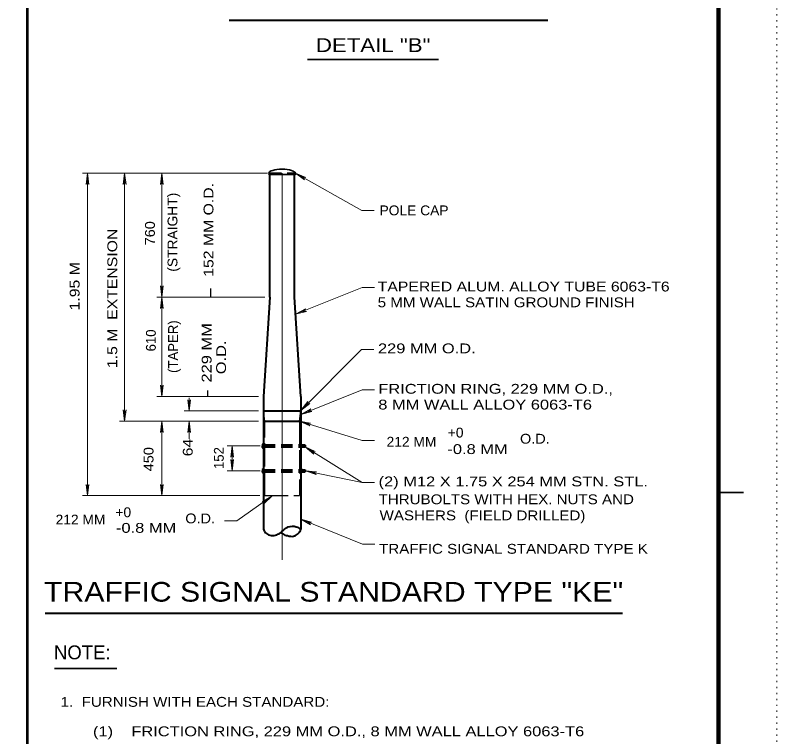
# Model space of a CAD drawing. Extents: x 312583 to 312854, y 144419 to 144597.
# Drawn here: x 312794.6 to 312853.5, y 144484.7 to 144540.5 of the extents above; entities that cross this region are included whole.
import ezdxf

# ---------------------------------------------------------------- set-up
doc = ezdxf.new("R2010")
doc.units = 0
doc.header["$LTSCALE"] = 0.3
for name, pattern in [('DOTTED', [1.5, 0.3, -1.2]), ('LONG_DASHED', [7.5, 6, -1.5]), ('MEDIUM_DASHED', [4.5, 3, -1.5])]:
    doc.linetypes.add(name, pattern=pattern)
for name, color, linetype, lineweight in [('1', 7, 'Continuous', 40), ('2', 7, 'Continuous', 13), ('62', 7, 'DOTTED', 13)]:
    doc.layers.add(name, color=color, linetype=linetype, lineweight=lineweight)

msp = doc.modelspace()

# ---------------------------------------------------------------- linework, layer by layer
at = {"layer": '1', "lineweight": 158}
msp.add_line((312849, 144423.1446), (312849, 144585.0846), dxfattribs=at)
at = {"layer": '1', "lineweight": 35}
for p, q in [((312814.2381, 144528.2019), (312814.2381, 144528.2709)), ((312813.7934, 144507.0803), (312813.8011, 144507.0803)), ((312813.7934, 144505.1636), (312813.8011, 144505.1636)), ((312849, 144503.6216), (312850.932, 144503.6216))]:
    msp.add_line(p, q, dxfattribs=at)
at = {"layer": '1', "linetype": 'MEDIUM_DASHED', "lineweight": 35}
for p, q in [((312814.2994, 144528.3016), (312816.2161, 144528.3016)), ((312814.2994, 144528.2019), (312814.2994, 144528.3016)), ((312816.2161, 144528.3016), (312816.2161, 144528.2019))]:
    msp.add_line(p, q, dxfattribs=at)
at = {"layer": '1', "lineweight": 25}
for p, q in [((312809.7454, 144518.7183), (312809.7454, 144519.4006)), ((312809.5077, 144511.0516), (312809.5077, 144511.5039))]:
    msp.add_line(p, q, dxfattribs=at)
at = {"layer": '1'}
for p, q in [((312813.7321, 144507.3256), (312813.7321, 144507.2183)), ((312813.7321, 144507.1109), (312813.7321, 144507.2259)), ((312813.7397, 144507.3563), (312813.8241, 144507.3563)), ((312813.7397, 144507.2873), (312813.8241, 144507.2873)), ((312813.7397, 144507.1493), (312813.8241, 144507.1493)), ((312813.7397, 144507.0803), (312813.8241, 144507.0803)), ((312816.7834, 144507.3563), (312816.6991, 144507.3563)), ((312816.7834, 144507.2873), (312816.6991, 144507.2873)), ((312816.7834, 144507.1569), (312816.6991, 144507.1569)), ((312816.7834, 144507.0879), (312816.6991, 144507.0879)), ((312816.7911, 144507.3256), (312816.7911, 144507.2183)), ((312816.7911, 144507.1109), (312816.7911, 144507.2183)), ((312813.7321, 144505.4089), (312813.7321, 144505.3016)), ((312813.7321, 144505.1943), (312813.7321, 144505.3093)), ((312813.7397, 144505.4396), (312813.8241, 144505.4396)), ((312813.7397, 144505.3706), (312813.8241, 144505.3706)), ((312813.7397, 144505.2326), (312813.8241, 144505.2326)), ((312813.7397, 144505.1636), (312813.8241, 144505.1636)), ((312816.7834, 144505.4396), (312816.6991, 144505.4396)), ((312816.7834, 144505.3706), (312816.6991, 144505.3706)), ((312816.7834, 144505.2403), (312816.6991, 144505.2403)), ((312816.7834, 144505.1713), (312816.6991, 144505.1713)), ((312816.7911, 144505.4089), (312816.7911, 144505.3016)), ((312816.7911, 144505.1943), (312816.7911, 144505.3016))]:
    msp.add_line(p, q, dxfattribs=at)
at = {"layer": '1', "lineweight": 53}
msp.add_lwpolyline([(312849, 144468.4167), (312795.5728, 144468.4167), (312795.5728, 144585.0846)], dxfattribs=at)
at = {"layer": '1', "lineweight": 35}
for points in [[(312814.2381, 144528.2019), (312814.2994, 144528.2019), (312816.2161, 144528.2019)], [(312816.2851, 144528.3016), (312816.2851, 144528.2709), (312816.2851, 144528.2019), (312816.2161, 144528.2019)]]:
    msp.add_lwpolyline(points, dxfattribs=at)
at = {"layer": '1'}
for centre, radius, start, end in [((312814.0192, 144507.2119), 0.291, 164.99798, 178.595), ((312814.0192, 144507.2262), 0.291, 181.405, 195.00202), ((312813.7848, 144507.324), 0.0563, 145.8703, 178.33743), ((312813.7848, 144507.1141), 0.0563, 181.66257, 214.1297), ((312813.8862, 144507.3512), 0.1612, 192.17822, 203.35152), ((312813.8862, 144507.0869), 0.1612, 156.63419, 167.82178), ((312816.635, 144507.3528), 0.1612, 336.63419, 347.82178), ((312816.635, 144507.0886), 0.1612, 12.17822, 23.35152), ((312816.7365, 144507.3256), 0.0563, 1.66257, 34.1297), ((312816.502, 144507.2135), 0.291, 1.405, 15.00202), ((312816.502, 144507.2278), 0.291, 344.99798, 358.595), ((312816.7365, 144507.1157), 0.0563, 325.8703, 358.33743), ((312814.0192, 144505.2952), 0.291, 164.99798, 178.595), ((312814.0192, 144505.3095), 0.291, 181.405, 195.00202), ((312813.7848, 144505.4073), 0.0563, 145.8703, 178.33743), ((312813.7848, 144505.1974), 0.0563, 181.66257, 214.1297), ((312813.8862, 144505.4345), 0.1612, 192.17822, 203.35152), ((312813.8862, 144505.1702), 0.1612, 156.63419, 167.82178), ((312816.635, 144505.4362), 0.1612, 336.63419, 347.82178), ((312816.635, 144505.1719), 0.1612, 12.17822, 23.35152), ((312816.7365, 144505.409), 0.0563, 1.66257, 34.1297), ((312816.502, 144505.2969), 0.291, 1.405, 15.00202), ((312816.502, 144505.3112), 0.291, 344.99798, 358.595), ((312816.7365, 144505.1991), 0.0563, 325.8703, 358.33743)]:
    msp.add_arc(centre, radius, start, end, dxfattribs=at)
at = {"layer": '1', "lineweight": 35}
msp.add_ellipse((312815.2606, 144528.3013), major_axis=(-1.0216, 0.0016), ratio=0.302378, start_param=3.1415927, end_param=6.2831853, dxfattribs=at)
at = {"layer": '2', "lineweight": 40}
for p, q in [((312811.1573, 144540.1302), (312835.7979, 144540.1302)), ((312814.2994, 144518.7183), (312814.2994, 144528.2019)), ((312816.2161, 144518.7183), (312816.2161, 144528.2019)), ((312814.2994, 144518.7183), (312813.8241, 144511.0516)), ((312816.6991, 144511.0516), (312816.2161, 144518.7183)), ((312813.8241, 144511.0516), (312813.8241, 144509.9323)), ((312816.6991, 144511.0516), (312816.6991, 144509.9323)), ((312813.8241, 144509.9323), (312813.8241, 144500.7783)), ((312813.8241, 144509.1349), (312816.6991, 144509.1349)), ((312816.7911, 144507.3026), (312817.0134, 144507.3026)), ((312816.7911, 144507.1416), (312817.0134, 144507.1416)), ((312816.8217, 144507.3026), (312816.8217, 144507.1416)), ((312816.8524, 144507.2643), (312816.8524, 144507.1723)), ((312816.8831, 144507.3026), (312816.8831, 144507.1416)), ((312816.9137, 144507.2643), (312816.9137, 144507.1723)), ((312816.9444, 144507.3026), (312816.9444, 144507.1416)), ((312816.9827, 144507.2643), (312816.9827, 144507.1723)), ((312817.0134, 144507.3026), (312817.0134, 144507.1416)), ((312817.0134, 144507.3026), (312817.0441, 144507.2796)), ((312817.0441, 144507.1646), (312817.0134, 144507.1416)), ((312817.0441, 144507.2796), (312817.0441, 144507.1646)), ((312816.7911, 144505.3859), (312817.0134, 144505.3859)), ((312816.7911, 144505.2249), (312817.0134, 144505.2249)), ((312816.8217, 144505.3859), (312816.8217, 144505.2249)), ((312816.8524, 144505.3476), (312816.8524, 144505.2556)), ((312816.8831, 144505.3859), (312816.8831, 144505.2249)), ((312816.9137, 144505.3476), (312816.9137, 144505.2556)), ((312816.9444, 144505.3859), (312816.9444, 144505.2249)), ((312816.9827, 144505.3476), (312816.9827, 144505.2556)), ((312817.0134, 144505.3859), (312817.0134, 144505.2249)), ((312817.0134, 144505.3859), (312817.0441, 144505.3629)), ((312817.0134, 144505.2249), (312817.0441, 144505.2479)), ((312817.0441, 144505.3629), (312817.0441, 144505.2479)), ((312796.9284, 144494.2929), (312841.5717, 144494.2929))]:
    msp.add_line(p, q, dxfattribs=at)
at = {"layer": '2', "lineweight": 35}
for p, q in [((312817.2197, 144537.0865), (312827.349, 144537.0865)), ((312797.6556, 144490.0086), (312802.4688, 144490.0086))]:
    msp.add_line(p, q, dxfattribs=at)
at = {"layer": '2'}
for p, q in [((312814.1231, 144528.3016), (312799.8247, 144528.3016)), ((312800.2081, 144528.3016), (312800.1007, 144527.4353)), ((312800.2081, 144528.3016), (312800.2081, 144503.3849)), ((312800.2081, 144528.3016), (312800.3154, 144527.4353)), ((312803.0831, 144528.3016), (312802.9757, 144527.4353)), ((312803.0831, 144528.3016), (312803.0831, 144509.1349)), ((312803.0831, 144528.3016), (312803.1904, 144527.4353)), ((312805.9581, 144528.3016), (312805.8507, 144527.4353)), ((312805.9581, 144528.3016), (312806.0654, 144527.4353)), ((312815.2577, 144498.4246), (312815.2577, 144528.3016)), ((312816.2851, 144528.3093), (312816.9827, 144527.7803)), ((312816.2851, 144528.3093), (312817.0901, 144527.9719)), ((312816.9827, 144527.7803), (312816.7911, 144528.0103)), ((312817.0901, 144527.9719), (312816.7911, 144528.0103)), ((312800.1007, 144527.4353), (312800.2081, 144527.7113)), ((312800.3154, 144527.4353), (312800.2081, 144527.7113)), ((312802.9757, 144527.4353), (312803.0831, 144527.7113)), ((312803.1904, 144527.4353), (312803.0831, 144527.7113)), ((312805.8507, 144527.4353), (312805.9581, 144527.7113)), ((312806.0654, 144527.4353), (312805.9581, 144527.7113)), ((312805.8507, 144519.5846), (312805.9581, 144519.3086)), ((312805.9581, 144518.7183), (312805.8507, 144519.5846)), ((312806.0654, 144519.5846), (312805.9581, 144519.3086)), ((312805.9581, 144518.7183), (312806.0654, 144519.5846)), ((312816.3004, 144517.3996), (312821.4524, 144519.4696)), ((312821.4524, 144519.4696), (312822.4107, 144519.4696)), ((312805.5747, 144518.7183), (312813.9161, 144518.7183)), ((312805.9581, 144518.7183), (312805.8507, 144517.8519)), ((312805.9581, 144518.7183), (312806.0654, 144517.8519)), ((312805.8507, 144517.8519), (312805.9581, 144518.1279)), ((312806.0654, 144517.8519), (312805.9581, 144518.1279)), ((312816.3004, 144517.3996), (312817.0671, 144517.8213)), ((312816.3004, 144517.3996), (312817.1437, 144517.6219)), ((312817.0671, 144517.8213), (312816.8524, 144517.6143)), ((312817.1437, 144517.6219), (312816.8524, 144517.6143)), ((312816.7144, 144509.9706), (312821.3911, 144514.6779)), ((312821.3911, 144514.6779), (312822.3417, 144514.6779)), ((312805.8507, 144511.9179), (312805.9581, 144511.6419)), ((312805.9581, 144511.0516), (312805.8507, 144511.9179)), ((312806.0654, 144511.9179), (312805.9581, 144511.6419)), ((312805.9581, 144511.0516), (312806.0654, 144511.9179)), ((312816.7144, 144509.6563), (312821.4601, 144511.5653)), ((312821.4601, 144511.5653), (312822.4107, 144511.5653)), ((312805.5747, 144511.0516), (312813.4407, 144511.0516)), ((312808.0664, 144510.9289), (312808.0664, 144509.9323)), ((312807.9591, 144510.7986), (312808.0664, 144510.5226)), ((312808.0664, 144509.9323), (312807.9591, 144510.7986)), ((312808.1737, 144510.7986), (312808.0664, 144510.5226)), ((312808.0664, 144509.9323), (312808.1737, 144510.7986)), ((312816.7144, 144509.9706), (312817.2587, 144510.6606)), ((312816.7144, 144509.9706), (312817.4044, 144510.5073)), ((312817.2587, 144510.6606), (312817.1361, 144510.3923)), ((312817.4044, 144510.5073), (312817.1361, 144510.3923)), ((312802.9757, 144510.0013), (312803.0831, 144509.7253)), ((312803.0831, 144509.1349), (312802.9757, 144510.0013)), ((312803.1904, 144510.0013), (312803.0831, 144509.7253)), ((312803.0831, 144509.1349), (312803.1904, 144510.0013)), ((312807.6831, 144509.9323), (312813.4407, 144509.9323)), ((312816.7144, 144509.6563), (312817.4811, 144510.0779)), ((312816.7144, 144509.6563), (312817.5577, 144509.8786)), ((312817.4811, 144510.0779), (312817.2664, 144509.8786)), ((312817.5577, 144509.8786), (312817.2664, 144509.8786)), ((312802.6997, 144509.1349), (312813.4407, 144509.1349)), ((312805.9581, 144509.1349), (312805.8507, 144508.2686)), ((312805.9581, 144509.1349), (312805.9581, 144503.3849)), ((312805.9581, 144509.1349), (312806.0654, 144508.2686)), ((312808.0664, 144509.1349), (312807.9591, 144508.2686)), ((312808.0664, 144509.1349), (312808.1737, 144508.2686)), ((312808.0664, 144509.1349), (312808.0664, 144507.7832)), ((312816.5994, 144509.1349), (312821.4601, 144507.6399)), ((312816.5994, 144509.1349), (312817.4581, 144508.9893)), ((312816.5994, 144509.1349), (312817.3967, 144508.7823)), ((312805.8507, 144508.2686), (312805.9581, 144508.5446)), ((312806.0654, 144508.2686), (312805.9581, 144508.5446)), ((312807.9591, 144508.2686), (312808.0664, 144508.5446)), ((312808.1737, 144508.2686), (312808.0664, 144508.5446)), ((312817.4581, 144508.9893), (312817.1591, 144508.9663)), ((312817.3967, 144508.7823), (312817.1591, 144508.9663)), ((312821.4601, 144507.6399), (312822.4107, 144507.6399)), ((312813.5711, 144507.2183), (312811.0104, 144507.2183)), ((312811.3937, 144507.2183), (312811.2864, 144506.3519)), ((312811.3937, 144507.2183), (312811.3937, 144505.3016)), ((312811.3937, 144507.2183), (312811.5011, 144506.3519)), ((312817.0287, 144507.1493), (312817.8184, 144506.7813)), ((312817.0287, 144507.1493), (312817.7034, 144506.5973)), ((312817.8184, 144506.7813), (312817.5271, 144506.8349)), ((312817.7034, 144506.5973), (312817.5271, 144506.8349)), ((312811.2864, 144506.3519), (312811.3937, 144506.6279)), ((312811.5011, 144506.3519), (312811.3937, 144506.6279)), ((312811.2864, 144506.1679), (312811.3937, 144505.8919)), ((312811.3937, 144505.3016), (312811.2864, 144506.1679)), ((312811.5011, 144506.1679), (312811.3937, 144505.8919)), ((312811.3937, 144505.3016), (312811.5011, 144506.1679)), ((312813.5711, 144505.3016), (312811.0104, 144505.3016)), ((312817.0594, 144505.2939), (312817.9257, 144505.2173)), ((312817.0594, 144505.2939), (312817.8874, 144505.0103)), ((312817.9257, 144505.2173), (312817.6344, 144505.1713)), ((312817.8874, 144505.0103), (312817.6344, 144505.1713)), ((312800.1007, 144504.2513), (312800.2081, 144503.9753)), ((312800.2081, 144503.3849), (312800.1007, 144504.2513)), ((312800.3154, 144504.2513), (312800.2081, 144503.9753)), ((312800.2081, 144503.3849), (312800.3154, 144504.2513)), ((312805.8507, 144504.2513), (312805.9581, 144503.9753)), ((312805.9581, 144503.3849), (312805.8507, 144504.2513)), ((312806.0654, 144504.2513), (312805.9581, 144503.9753)), ((312805.9581, 144503.3849), (312806.0654, 144504.2513)), ((312821.4601, 144504.3893), (312822.4107, 144504.3893)), ((312799.8247, 144503.3849), (312813.5404, 144503.3849)), ((312811.7698, 144501.4376), (312814.4834, 144503.3619)), ((312814.4834, 144503.3619), (312813.7228, 144502.9312)), ((312814.4834, 144503.3619), (312813.8536, 144502.7588)), ((312813.7228, 144502.9312), (312814.0107, 144503.0123)), ((312813.8536, 144502.7588), (312814.0107, 144503.0123)), ((312816.6991, 144501.5526), (312817.5424, 144501.3226)), ((312816.6991, 144501.5526), (312817.4581, 144501.1233)), ((312821.4677, 144499.6283), (312816.6991, 144501.5526)), ((312811.7698, 144501.4376), (312810.8115, 144501.4376)), ((312817.5424, 144501.3226), (312817.2434, 144501.3303)), ((312817.4581, 144501.1233), (312817.2434, 144501.3303)), ((312821.4677, 144499.6283), (312822.4261, 144499.6283))]:
    msp.add_line(p, q, dxfattribs=at)
at = {"layer": '2', "linetype": 'LONG_DASHED', "lineweight": 25}
for p, q in [((312813.9237, 144509.1349), (312813.8241, 144509.9323)), ((312816.5994, 144509.1349), (312816.6991, 144509.9323)), ((312813.9237, 144503.3849), (312813.9237, 144509.1349)), ((312816.5994, 144509.1349), (312816.5994, 144503.3849)), ((312813.9237, 144503.3849), (312816.5994, 144503.3849))]:
    msp.add_line(p, q, dxfattribs=at)
at = {"layer": '2', "linetype": 'MEDIUM_DASHED', "lineweight": 40}
for p, q in [((312813.8241, 144507.3026), (312816.6991, 144507.3026)), ((312813.8241, 144507.1416), (312816.6991, 144507.1416)), ((312813.8241, 144505.3859), (312816.6991, 144505.3859)), ((312813.8241, 144505.2249), (312816.6991, 144505.2249))]:
    msp.add_line(p, q, dxfattribs=at)
at = {"layer": '2'}
for points in [[(312805.9581, 144528.3016), (312805.9581, 144518.7183), (312805.9581, 144511.0516)], [(312816.2851, 144528.3016), (312821.4217, 144525.4266), (312822.3801, 144525.4266)], [(312817.0594, 144507.1263), (312821.4601, 144504.3893), (312817.1667, 144505.2709)]]:
    msp.add_lwpolyline(points, dxfattribs=at)
at = {"layer": '2', "lineweight": 40}
msp.add_lwpolyline([(312813.8241, 144509.9323), (312816.6991, 144509.9323), (312816.6991, 144500.7783)], dxfattribs=at)
for points in [[(312813.8241, 144500.7783), (312813.9314, 144500.5713), (312814.1997, 144500.3566), (312814.6521, 144500.3029), (312815.0277, 144500.4409), (312815.4494, 144500.7783), (312815.7331, 144500.9623), (312816.3464, 144500.9776), (312816.6991, 144500.7783)], [(312815.1734, 144500.5483), (312815.3114, 144500.4179), (312815.6717, 144500.2876), (312816.1471, 144500.2493), (312816.4461, 144500.4103), (312816.6301, 144500.6096), (312816.6991, 144500.7783)]]:
    msp.add_spline(points, degree=3, dxfattribs=at)
at = {"layer": '62'}
msp.add_lwpolyline([(312601.2, 144418.5846), (312853.5, 144418.5846), (312853.5, 144596.7846)], dxfattribs=at)

# ---------------------------------------------------------------- texts
at = {"layer": '2'}
for s, height, width, p in [('DETAIL "B"', 1.07, 1.2, (312817.8728, 144537.6672)), ('POLE CAP', 0.76, 1.05, (312822.7893, 144525.0491)), ('TAPERED ALUM. ALLOY TUBE 6063-T6', 0.76, 1.2, (312822.6484, 144519.1619)), ('5 MM WALL SATIN GROUND FINISH', 0.76, 1.15, (312822.6484, 144517.9419)), ('229 MM O.D.', 0.76, 1.25, (312822.669, 144514.3823)), ('FRICTION RING, 229 MM O.D.,', 0.76, 1.25, (312822.6944, 144511.2576)), ('8 MM WALL ALLOY 6063-T6', 0.76, 1.25, (312822.6944, 144510.0376)), ('+0', 0.76, 1.05, (312828.0664, 144507.8734)), ('O.D.', 0.76, 1.1, (312833.6504, 144507.3986)), ('212 MM', 0.76, 1.05, (312823.334, 144507.1656)), ('-0.8 MM', 0.76, 1.25, (312828.0376, 144506.5959)), ('(2) M12 X 1.75 X 254 MM STN. STL.', 0.76, 1.25, (312822.7174, 144504.0969)), ('THRUBOLTS WITH HEX. NUTS AND', 0.76, 1.15, (312822.7174, 144502.7169)), ('+0', 0.76, 1.05, (312802.371, 144501.7146)), ('WASHERS  (FIELD DRILLED)', 0.76, 1.15, (312822.7941, 144501.4749)), ('212 MM', 0.76, 1.05, (312797.7464, 144501.1507)), ('O.D.', 0.76, 1.1, (312807.7755, 144501.2399)), ('-0.8 MM', 0.76, 1.25, (312802.4142, 144500.5091)), ('TRAFFIC SIGNAL STANDARD TYPE K', 0.76, 1.15, (312822.7557, 144498.8913)), ('TRAFFIC SIGNAL STANDARD TYPE "KE"', 1.52, 1.15, (312796.8509, 144495.1885)), ('1.  FURNISH WITH EACH STANDARD:', 0.76, 1.15, (312798.1381, 144487.0616)), ('(1)    FRICTION RING, 229 MM O.D., 8 MM WALL ALLOY 6063-T6', 0.76, 1.25, (312800.6374, 144484.7846))]:
    msp.add_text(s, height=height, dxfattribs=dict(at, width=width)).set_placement(p)
for s, width, p in [('152 MM O.D.', 1.2, (312809.9493, 144520.2967)), ('(STRAIGHT)', 1.05, (312807.1639, 144520.6881)), ('760', 1.1, (312805.4214, 144522.729)), ('1.5 M  EXTENSION', 1.2, (312802.5106, 144513.2408)), ('1.95 M', 1.2, (312799.5996, 144517.6958)), ('229 MM ', 1.25, (312809.8032, 144512.1244)), (' O.D. ', 1.25, (312810.9212, 144512.4121)), ('64 ', 1.2, (312808.3448, 144506.4197)), ('450', 1.1, (312805.3136, 144505.2656))]:
    msp.add_text(s, height=0.76, rotation=90, dxfattribs=dict(at, width=width)).set_placement(p)
for s, p in [('(TAPER)', (312807.2055, 144512.8646)), ('610', (312805.4933, 144514.5304)), ('152', (312810.7476, 144505.4358))]:
    msp.add_text(s, height=0.76, rotation=90, dxfattribs=at).set_placement(p)
msp.add_text('NOTE:', height=1.07, dxfattribs=at).set_placement((312797.622, 144490.7326))

doc.saveas('drawing.dxf')
